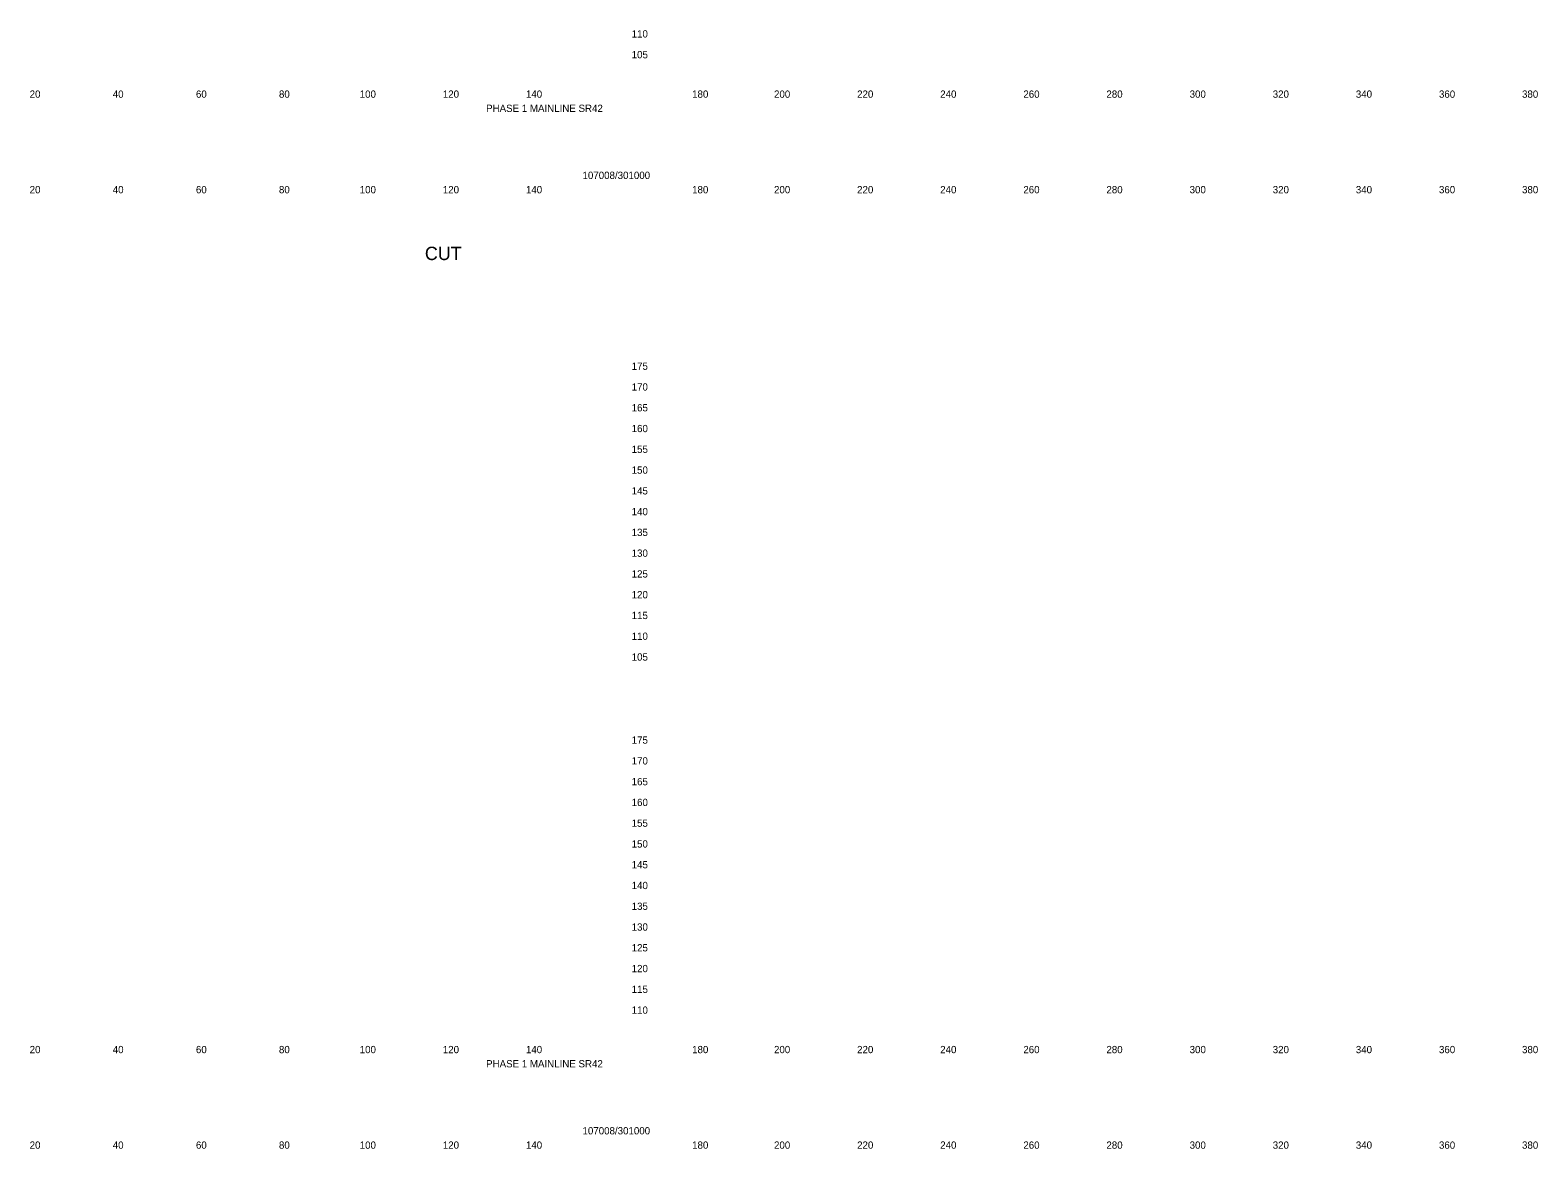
# Model space of a CAD drawing. Extents: x 21281 to 22024, y 6472 to 15198.
# Drawn here: x 21661.4 to 22024.2, y 12202.3 to 12471.6 of the extents above; entities that cross this region are included whole.
import ezdxf

# ---------------------------------------------------------------- set-up
doc = ezdxf.new("R2010")
doc.units = 0
doc.layers.add('XS_SHEET_LABELS_ELEVATION', color=7, linetype='Continuous')
doc.layers.add('XS_SHEET_LABELS_OFFSET', color=7, linetype='Continuous')

msp = doc.modelspace()

# ---------------------------------------------------------------- texts
at = {"layer": 'XS_SHEET_LABELS_ELEVATION'}
for s, p in [('  110  ', (21804.84, 12469.84)), ('  105  ', (21804.84, 12464.84)), ('  175  ', (21804.84, 12389.84)), ('  170  ', (21804.84, 12384.84)), ('  165  ', (21804.84, 12379.84)), ('  160  ', (21804.84, 12374.84)), ('  155  ', (21804.84, 12369.84)), ('  150  ', (21804.84, 12364.84)), ('  145  ', (21804.84, 12359.84)), ('  140  ', (21804.84, 12354.84)), ('  135  ', (21804.84, 12349.84)), ('  130  ', (21804.84, 12344.84)), ('  125  ', (21804.84, 12339.84)), ('  120  ', (21804.84, 12334.84)), ('  115  ', (21804.84, 12329.84)), ('  110  ', (21804.84, 12324.84)), ('  105  ', (21804.84, 12319.84)), ('  175  ', (21804.84, 12299.84)), ('  170  ', (21804.84, 12294.84)), ('  165  ', (21804.84, 12289.84)), ('  160  ', (21804.84, 12284.84)), ('  155  ', (21804.84, 12279.84)), ('  150  ', (21804.84, 12274.84)), ('  145  ', (21804.84, 12269.84)), ('  140  ', (21804.84, 12264.84)), ('  135  ', (21804.84, 12259.84)), ('  130  ', (21804.84, 12254.84)), ('  125  ', (21804.84, 12249.84)), ('  120  ', (21804.84, 12244.84)), ('  115  ', (21804.84, 12239.84)), ('  110  ', (21804.84, 12234.84))]:
    msp.add_text(s, height=1.75, dxfattribs=at).set_placement(p)
at = {"layer": 'XS_SHEET_LABELS_OFFSET'}
for s, height, p in [('  20  ', 1.75, (21659.95, 12455.34)), ('  40  ', 1.75, (21679.95, 12455.34)), ('  60  ', 1.75, (21699.97, 12455.34)), ('  80  ', 1.75, (21719.95, 12455.34)), ('  100  ', 1.75, (21739.39, 12455.34)), ('  120  ', 1.75, (21759.39, 12455.34)), ('PHASE 1 MAINLINE SR42', 1.75, (21771.11, 12451.92)), ('  140  ', 1.75, (21779.39, 12455.34)), ('  180  ', 1.75, (21819.39, 12455.34)), ('  200  ', 1.75, (21839.1, 12455.34)), ('  220  ', 1.75, (21859.1, 12455.34)), ('  240  ', 1.75, (21879.1, 12455.34)), ('  260  ', 1.75, (21899.11, 12455.34)), ('  280  ', 1.75, (21919.1, 12455.34)), ('  300  ', 1.75, (21939.13, 12455.34)), ('  320  ', 1.75, (21959.13, 12455.34)), ('  340  ', 1.75, (21979.13, 12455.34)), ('  360  ', 1.75, (21999.14, 12455.34)), ('  380  ', 1.75, (22019.13, 12455.34)), ('107008/301000', 1.75, (21794.31, 12435.79)), ('  20  ', 1.75, (21659.95, 12432.34)), ('  40  ', 1.75, (21679.95, 12432.34)), ('  60  ', 1.75, (21699.97, 12432.34)), ('  80  ', 1.75, (21719.95, 12432.34)), ('  100  ', 1.75, (21739.39, 12432.34)), ('  120  ', 1.75, (21759.39, 12432.34)), ('  140  ', 1.75, (21779.39, 12432.34)), ('  180  ', 1.75, (21819.39, 12432.34)), ('  200  ', 1.75, (21839.1, 12432.34)), ('  220  ', 1.75, (21859.1, 12432.34)), ('  240  ', 1.75, (21879.1, 12432.34)), ('  260  ', 1.75, (21899.11, 12432.34)), ('  280  ', 1.75, (21919.1, 12432.34)), ('  300  ', 1.75, (21939.13, 12432.34)), ('  320  ', 1.75, (21959.13, 12432.34)), ('  340  ', 1.75, (21979.13, 12432.34)), ('  360  ', 1.75, (21999.14, 12432.34)), ('  380  ', 1.75, (22019.13, 12432.34)), ('CUT', 3.222, (21756.37, 12416.26)), ('  20  ', 1.75, (21659.95, 12225.34)), ('  40  ', 1.75, (21679.95, 12225.34)), ('  60  ', 1.75, (21699.97, 12225.34)), ('  80  ', 1.75, (21719.95, 12225.34)), ('  100  ', 1.75, (21739.39, 12225.34)), ('  120  ', 1.75, (21759.39, 12225.34)), ('  140  ', 1.75, (21779.39, 12225.34)), ('  180  ', 1.75, (21819.39, 12225.34)), ('  200  ', 1.75, (21839.1, 12225.34)), ('  220  ', 1.75, (21859.1, 12225.34)), ('  240  ', 1.75, (21879.1, 12225.34)), ('  260  ', 1.75, (21899.11, 12225.34)), ('  280  ', 1.75, (21919.1, 12225.34)), ('  300  ', 1.75, (21939.13, 12225.34)), ('  320  ', 1.75, (21959.13, 12225.34)), ('  340  ', 1.75, (21979.13, 12225.34)), ('  360  ', 1.75, (21999.14, 12225.34)), ('  380  ', 1.75, (22019.13, 12225.34)), ('PHASE 1 MAINLINE SR42', 1.75, (21771.11, 12221.92)), ('107008/301000', 1.75, (21794.31, 12205.79)), ('  20  ', 1.75, (21659.95, 12202.34)), ('  40  ', 1.75, (21679.95, 12202.34)), ('  60  ', 1.75, (21699.97, 12202.34)), ('  80  ', 1.75, (21719.95, 12202.34)), ('  100  ', 1.75, (21739.39, 12202.34)), ('  120  ', 1.75, (21759.39, 12202.34)), ('  140  ', 1.75, (21779.39, 12202.34)), ('  180  ', 1.75, (21819.39, 12202.34)), ('  200  ', 1.75, (21839.1, 12202.34)), ('  220  ', 1.75, (21859.1, 12202.34)), ('  240  ', 1.75, (21879.1, 12202.34)), ('  260  ', 1.75, (21899.11, 12202.34)), ('  280  ', 1.75, (21919.1, 12202.34)), ('  300  ', 1.75, (21939.13, 12202.34)), ('  320  ', 1.75, (21959.13, 12202.34)), ('  340  ', 1.75, (21979.13, 12202.34)), ('  360  ', 1.75, (21999.14, 12202.34)), ('  380  ', 1.75, (22019.13, 12202.34))]:
    msp.add_text(s, height=height, dxfattribs=at).set_placement(p)

doc.saveas('drawing.dxf')
